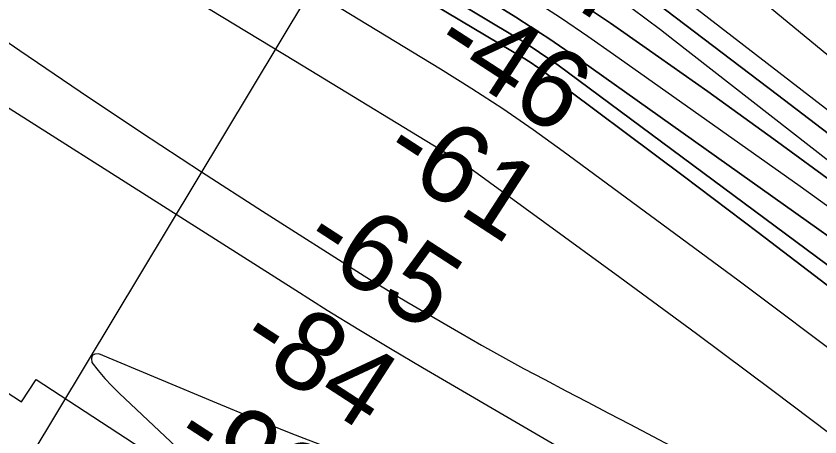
# Model space of a CAD drawing. Extents: x 3568792 to 3606828, y 529143 to 554785.
# Drawn here: x 3573791 to 3574473, y 543580 to 543937 of the extents above; entities that cross this region are included whole.
import ezdxf

# ---------------------------------------------------------------- set-up
doc = ezdxf.new("R2010")
doc.units = 0
for name, color, linetype in [('V-RIVR-RANG', 7, 'Continuous'), ('V-RRAP-RVMT', 7, 'Continuous'), ('V-TOPO-DPTH', 7, 'Continuous'), ('V-TOPO-MAJR', 7, 'Continuous'), ('V-TOPO-MINR', 7, 'Continuous'), ('V-TOPO-WATR', 7, 'Continuous')]:
    doc.layers.add(name, color=color, linetype=linetype)

msp = doc.modelspace()

# ---------------------------------------------------------------- linework, layer by layer
at = {"layer": 'V-RIVR-RANG'}
msp.add_line((3574243.89, 544295.63), (3573728.04, 543438.94), dxfattribs=at)
at = {"layer": 'V-RRAP-RVMT'}
for p, q in [((3573692.14, 543676.98), (3573795.47, 543609.83)), ((3573795.47, 543609.83), (3573808.13, 543628.75)), ((3573808.13, 543628.75), (3573897.64, 543570.1))]:
    msp.add_line(p, q, dxfattribs=at)
at = {"layer": 'V-TOPO-DPTH'}
for points in [[(3575079.98, 543409.78), (3574376.61, 543989.15), (3574348.05, 544012.13), (3574319.16, 544034.67), (3574289.75, 544056.54), (3574260.01, 544077.96), (3574236.95, 544094.17), (3574195.02, 544122.73), (3574152.56, 544150.44), (3574109.29, 544176.88), (3574065.49, 544202.47), (3573222.09, 544678.59)], [(3575585.53, 542914.64), (3575478.26, 543004.3), (3575370.54, 543093.43), (3575150.41, 543274.17), (3575136.84, 543285.25), (3575123.22, 543296.26), (3575109.53, 543307.18), (3575095.79, 543318.05), (3574599.35, 543708.04), (3574544.81, 543750.22), (3574489.85, 543791.85), (3574434.27, 543832.64), (3574378.27, 543872.87), (3574325.99, 543909.84), (3574295.65, 543930.9), (3574265.07, 543951.61), (3574234.13, 543971.79), (3574202.97, 543991.62), (3574121.19, 544042.65), (3574048.63, 544087.16), (3573975.63, 544130.93), (3573901.97, 544173.59), (3573827.88, 544215.5), (3573167.14, 544582.65)], [(3573167.14, 544582.65), (3573827.88, 544215.5), (3573901.97, 544173.59), (3573975.63, 544130.93), (3574048.63, 544087.16), (3574121.19, 544042.65), (3574202.97, 543991.62), (3574234.13, 543971.79), (3574265.07, 543951.61), (3574295.65, 543930.9), (3574325.99, 543909.84), (3574378.27, 543872.87), (3574434.27, 543832.64), (3574489.85, 543791.85), (3574544.81, 543750.22), (3574599.35, 543708.04), (3575095.79, 543318.05), (3575109.53, 543307.18), (3575123.22, 543296.26), (3575136.84, 543285.25), (3575150.41, 543274.17), (3575370.54, 543093.43), (3575478.26, 543004.3), (3575585.53, 542914.64)], [(3573542.9, 544321.23), (3574219.33, 543916.4), (3574227.44, 543911.38), (3574235.45, 543906.21), (3574243.3, 543900.8), (3574251.05, 543895.23), (3574910.2, 543406.72), (3574941.62, 543383.19), (3574972.89, 543359.46), (3575003.92, 543335.42), (3575034.79, 543311.18), (3575062.59, 543289.14), (3575079.39, 543275.7), (3575096.11, 543262.16), (3575112.72, 543248.48), (3575129.26, 543234.71), (3575145.7, 543220.83), (3575162.08, 543206.88), (3575178.4, 543192.86), (3575194.67, 543178.77), (3575925.84, 542542.13)], [(3575925.84, 542542.13), (3575194.67, 543178.77), (3575178.4, 543192.86), (3575162.08, 543206.88), (3575145.7, 543220.83), (3575129.26, 543234.71), (3575112.72, 543248.48), (3575096.11, 543262.16), (3575079.39, 543275.7), (3575062.59, 543289.14), (3575034.79, 543311.18), (3575003.92, 543335.42), (3574972.89, 543359.46), (3574941.62, 543383.19), (3574910.2, 543406.72), (3574251.05, 543895.23), (3574243.3, 543900.8), (3574235.45, 543906.21), (3574227.44, 543911.38), (3574219.33, 543916.4), (3573542.9, 544321.23)], [(3573607.03, 544311.45), (3574215.16, 543935.91), (3574229.21, 543927.04), (3574243.15, 543918), (3574256.9, 543908.7), (3574270.54, 543899.21), (3574683.21, 543606.36), (3574755.83, 543553.88), (3574827.82, 543500.58), (3574898.88, 543446.04), (3574969.33, 543390.68), (3575099.57, 543286.49), (3575104.41, 543282.59), (3575109.23, 543278.66), (3575114.02, 543274.69), (3575118.79, 543270.7), (3575716.35, 542767.37)], [(3575716.35, 542767.37), (3575118.79, 543270.7), (3575114.02, 543274.69), (3575109.23, 543278.66), (3575104.41, 543282.59), (3575099.57, 543286.49), (3574969.33, 543390.68), (3574898.88, 543446.04), (3574827.82, 543500.58), (3574755.83, 543553.88), (3574683.21, 543606.36), (3574270.54, 543899.21), (3574256.9, 543908.7), (3574243.15, 543918), (3574229.21, 543927.04), (3574215.16, 543935.91), (3573607.03, 544311.45)], [(3576025.9, 542593.42), (3575500.51, 543026.99), (3575440.92, 543076), (3575381.22, 543124.88), (3575321.36, 543173.56), (3575261.39, 543222.11), (3575191.02, 543278.88), (3575166.13, 543298.9), (3575141.19, 543318.87), (3575116.19, 543338.76), (3575091.14, 543358.59), (3574736.89, 543638.26), (3574662.41, 543696.72), (3574587.72, 543754.9), (3574512.7, 543812.66), (3574437.46, 543870.15), (3574296.51, 543977.23), (3574291.53, 543980.88), (3574286.48, 543984.42), (3574281.31, 543987.78), (3574276.06, 543991.03), (3574027.1, 544139.56), (3573896.99, 544216.42), (3573766.46, 544292.55)], [(3573766.46, 544292.55), (3573896.99, 544216.42), (3574027.1, 544139.56), (3574276.06, 543991.03), (3574281.31, 543987.78), (3574286.48, 543984.42), (3574291.53, 543980.88), (3574296.51, 543977.23), (3574437.46, 543870.15), (3574512.7, 543812.66), (3574587.72, 543754.9), (3574662.41, 543696.72), (3574736.89, 543638.26), (3575091.14, 543358.59), (3575116.19, 543338.76), (3575141.19, 543318.87), (3575166.13, 543298.9), (3575191.02, 543278.88), (3575261.39, 543222.11), (3575321.36, 543173.56), (3575381.22, 543124.88), (3575440.92, 543076), (3575500.51, 543026.99), (3576025.9, 542593.42)], [(3573775.52, 544155.9), (3573852.41, 544114.96), (3573928.81, 544073.16), (3574004.48, 544030.05), (3574079.67, 543986.07), (3574222.97, 543900.59), (3574226.11, 543898.65), (3574229.21, 543896.64), (3574232.25, 543894.55), (3574235.25, 543892.39), (3574357.29, 543801.49), (3574420.99, 543753.48), (3574484.33, 543704.98), (3574547.11, 543655.77), (3574609.52, 543606.09), (3575030.88, 543266.67), (3575051.81, 543249.72), (3575072.68, 543232.69), (3575093.46, 543215.54), (3575114.18, 543198.32), (3575249.44, 543085.24), (3575337.32, 543010.93), (3575424.61, 542935.95)], [(3573775.52, 544155.9), (3573852.41, 544114.96), (3573928.81, 544073.16), (3574004.48, 544030.05), (3574079.67, 543986.07), (3574222.97, 543900.59), (3574226.11, 543898.65), (3574229.21, 543896.64), (3574232.25, 543894.55), (3574235.25, 543892.39), (3574357.29, 543801.49), (3574420.99, 543753.48), (3574484.33, 543704.98), (3574547.11, 543655.77), (3574609.52, 543606.09), (3575030.88, 543266.67), (3575051.81, 543249.72), (3575072.68, 543232.69), (3575093.46, 543215.54), (3575114.18, 543198.32), (3575249.44, 543085.24), (3575337.32, 543010.93), (3575424.61, 542935.95)]]:
    msp.add_lwpolyline(points, dxfattribs=at)
at = {"layer": 'V-TOPO-MAJR'}
msp.add_lwpolyline([(3575551.68, 542785.81), (3575063.53, 543193.18), (3575056.83, 543198.74), (3575050.11, 543204.29), (3575043.36, 543209.8), (3575036.6, 543215.29), (3574794.28, 543411.22), (3574697.79, 543488.17), (3574600.63, 543564.24), (3574502.46, 543639.01), (3574403.61, 543712.9), (3574255.37, 543822.17), (3574229.9, 543840.42), (3574204.12, 543858.21), (3574177.87, 543875.3), (3574151.3, 543891.92), (3573958.78, 544008.86), (3573835.19, 544082.67), (3573710.88, 544155.24)], dxfattribs=at)
at = {"layer": 'V-TOPO-MINR'}
for points in [[(3575079.98, 543409.78), (3574376.61, 543989.15), (3574348.05, 544012.13), (3574319.16, 544034.67), (3574289.75, 544056.54), (3574260.01, 544077.96), (3574236.95, 544094.17), (3574195.02, 544122.73), (3574152.56, 544150.44), (3574109.29, 544176.88), (3574065.49, 544202.47), (3573222.09, 544678.59)], [(3575568.29, 542949.44), (3575481.55, 543021.63), (3575394.4, 543093.33), (3575306.97, 543164.7), (3575169.36, 543276.39), (3575150.49, 543291.61), (3575131.56, 543306.75), (3575112.54, 543321.79), (3575093.46, 543336.75), (3574350.04, 543916.05), (3574338.05, 543925.26), (3574325.97, 543934.35), (3574313.77, 543943.28), (3574301.47, 543952.08), (3574289.05, 543960.7), (3574276.54, 543969.18), (3574263.88, 543977.45), (3574251.14, 543985.59), (3574245.7, 543989), (3574230.11, 543998.63), (3574214.42, 544008.11), (3574198.61, 544017.37), (3574182.71, 544026.49), (3573186.15, 544588.81)], [(3575585.53, 542914.64), (3575478.26, 543004.3), (3575370.54, 543093.43), (3575150.41, 543274.17), (3575136.84, 543285.25), (3575123.22, 543296.26), (3575109.53, 543307.18), (3575095.79, 543318.05), (3574599.35, 543708.04), (3574544.81, 543750.22), (3574489.85, 543791.85), (3574434.27, 543832.64), (3574378.27, 543872.87), (3574325.99, 543909.84), (3574295.65, 543930.9), (3574265.07, 543951.61), (3574234.13, 543971.79), (3574202.97, 543991.62), (3574121.19, 544042.65), (3574048.63, 544087.16), (3573975.63, 544130.93), (3573901.97, 544173.59), (3573827.88, 544215.5), (3573167.14, 544582.65)], [(3575556.87, 543003.8), (3575351.9, 543169.52), (3575318.47, 543196.54), (3575285.03, 543223.54), (3575251.57, 543250.52), (3575218.11, 543277.5), (3575213.28, 543281.39), (3575182.21, 543306.39), (3575151.13, 543331.38), (3575120.02, 543356.34), (3575088.91, 543381.28), (3575015.32, 543440.2), (3574947.26, 543494.4), (3574879, 543548.35), (3574810.45, 543601.94), (3574741.71, 543655.29), (3574319.54, 543981.07), (3574307.66, 543989.88), (3574295.59, 543998.39), (3574283.2, 544006.45), (3574270.61, 544014.21), (3573321.53, 544574.65)], [(3575925.84, 542542.13), (3575194.67, 543178.77), (3575178.4, 543192.86), (3575162.08, 543206.88), (3575145.7, 543220.83), (3575129.26, 543234.71), (3575112.72, 543248.48), (3575096.11, 543262.16), (3575079.39, 543275.7), (3575062.59, 543289.14), (3575034.79, 543311.18), (3575003.92, 543335.42), (3574972.89, 543359.46), (3574941.62, 543383.19), (3574910.2, 543406.72), (3574251.05, 543895.23), (3574243.3, 543900.8), (3574235.45, 543906.21), (3574227.44, 543911.38), (3574219.33, 543916.4), (3573542.9, 544321.23)], [(3575716.35, 542767.37), (3575118.79, 543270.7), (3575114.02, 543274.69), (3575109.23, 543278.66), (3575104.41, 543282.59), (3575099.57, 543286.49), (3574969.33, 543390.68), (3574898.88, 543446.04), (3574827.82, 543500.58), (3574755.83, 543553.88), (3574683.21, 543606.36), (3574270.54, 543899.21), (3574256.9, 543908.7), (3574243.15, 543918), (3574229.21, 543927.04), (3574215.16, 543935.91), (3573607.03, 544311.45)], [(3575540.19, 542934.14), (3575133.45, 543272.27), (3575124.61, 543279.57), (3575115.73, 543286.83), (3575106.8, 543294.03), (3575097.83, 543301.18), (3574852.56, 543495.55), (3574754.96, 543571.63), (3574656.55, 543646.63), (3574556.95, 543720.04), (3574456.55, 543792.39), (3574298.26, 543904.51), (3574276.27, 543919.79), (3574254.1, 543934.8), (3574231.66, 543949.4), (3574209.04, 543963.73), (3573989.42, 544100.09), (3573856.26, 544181.4), (3573722.33, 544261.39)], [(3575424.61, 542935.95), (3575337.32, 543010.93), (3575249.44, 543085.24), (3575114.18, 543198.32), (3575093.46, 543215.54), (3575072.68, 543232.69), (3575051.81, 543249.72), (3575030.88, 543266.67), (3574609.52, 543606.09), (3574547.11, 543655.77), (3574484.33, 543704.98), (3574420.99, 543753.48), (3574357.29, 543801.49), (3574235.25, 543892.39), (3574232.25, 543894.55), (3574229.21, 543896.64), (3574226.11, 543898.65), (3574222.97, 543900.59), (3574079.67, 543986.07), (3574004.48, 544030.05), (3573928.81, 544073.16), (3573852.41, 544114.96), (3573775.52, 544155.9)], [(3575297.07, 542944.57), (3575251.49, 542982.28), (3575205.79, 543019.85), (3575159.92, 543057.21), (3575113.94, 543094.44), (3575077.79, 543123.58), (3575049.73, 543146.04), (3575021.56, 543168.37), (3574993.23, 543190.49), (3574964.8, 543212.48), (3574562.28, 543521.56), (3574498.01, 543570.52), (3574433.5, 543619.17), (3574368.63, 543667.33), (3574303.51, 543715.17), (3574176.3, 543807.9), (3574174.59, 543809.11), (3574171.12, 543811.43), (3574169.34, 543812.55), (3574028.23, 543898.57), (3573955.67, 543942.29), (3573882.81, 543985.5), (3573809.5, 544027.95), (3573735.89, 544069.89)], [(3573628.65, 544021.3), (3573794.25, 543907.69), (3573845.33, 543873.04), (3573896.65, 543838.75), (3573948.31, 543805), (3574000.22, 543771.6), (3574086.47, 543716.74), (3574095.46, 543711.09), (3574104.49, 543705.52), (3574113.58, 543700.06), (3574122.72, 543694.66), (3574168.45, 543668.02), (3574186.12, 543657.89), (3574203.87, 543647.92), (3574221.76, 543638.19), (3574239.74, 543628.63), (3574257.78, 543619.18), (3574275.82, 543609.72), (3574293.84, 543600.24), (3574311.86, 543590.74), (3574435.53, 543525.5), (3574514.11, 543481.4)], [(3574520.71, 543416.15), (3574448.52, 543457.51), (3574376.39, 543498.99), (3574304.38, 543540.66), (3574232.43, 543582.46), (3574135.99, 543638.65), (3574108.86, 543654.66), (3574081.86, 543670.87), (3574055.04, 543687.38), (3574028.35, 543704.09), (3573661.67, 543936.58)], [(3574056.12, 543570.74), (3574024.4, 543583.04), (3573992.84, 543595.73), (3573961.38, 543608.68), (3573861.27, 543650.63), (3573857.85, 543650.33), (3573855.55, 543649.15), (3573854.92, 543646.64), (3573855.42, 543643.24), (3573860.74, 543636.33), (3573866.3, 543629.64), (3573872.23, 543623.28), (3573878.41, 543617.13), (3573941.79, 543557.53)]]:
    msp.add_lwpolyline(points, dxfattribs=at)
at = {"layer": 'V-TOPO-WATR'}
msp.add_lwpolyline([(3576025.9, 542593.42), (3575500.51, 543026.99), (3575440.92, 543076), (3575381.22, 543124.88), (3575321.36, 543173.56), (3575261.39, 543222.11), (3575191.02, 543278.88), (3575166.13, 543298.9), (3575141.19, 543318.87), (3575116.19, 543338.76), (3575091.14, 543358.59), (3574736.89, 543638.26), (3574662.41, 543696.72), (3574587.72, 543754.9), (3574512.7, 543812.66), (3574437.46, 543870.15), (3574296.51, 543977.23), (3574291.53, 543980.88), (3574286.48, 543984.42), (3574281.31, 543987.78), (3574276.06, 543991.03), (3574027.1, 544139.56), (3573896.99, 544216.42), (3573766.46, 544292.55)], dxfattribs=at)

# ---------------------------------------------------------------- texts
at = {"layer": 'V-RIVR-RANG'}
for s, p in [('-4', (3574220.53, 543972.97)), ('-46', (3574141.32, 543905.16)), ('-61', (3574098.4, 543813.8)), ('-65', (3574030.7, 543738.53)), ('-84', (3573976.71, 543654.35)), ('-92', (3573920.52, 543571.61))]:
    msp.add_text(s, height=67, rotation=327.01567, dxfattribs=at).set_placement(p)

doc.saveas('drawing.dxf')
